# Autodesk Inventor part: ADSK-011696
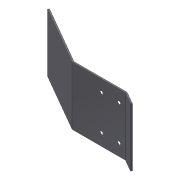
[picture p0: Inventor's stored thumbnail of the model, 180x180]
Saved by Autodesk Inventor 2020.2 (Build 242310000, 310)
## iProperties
Created: 2000-03
Part Number: ADSK-011696
Document SubType Name: Modeling
Designer: sspink
Material: Pearson Stainless Steel
Density: 1 g/cm^3
Sheet Metal Rule: Stahlblech 1.0312 - DC05 -   3.0 mm
Appearance: Pearson-Stainless
Mass: 126.696 g
Surface Area: 877.094 cm^2
Volume: 126.696 cm^3
Flat Pattern Width: 12.7 cm
Flat Pattern Length: 33.4701 cm
Flat Pattern Area: 425.07 cm^2
Sheet Metal Width: 127,000 mm
Sheet Metal Length: 334,701 mm
Sheet Metal Area: 42507,003 mm^2
Control State: 0
Master: False
Checked Out: False
Shininess: 57.0
Length Units: 11269
Angle Units: 11279
Time Units: 11290
Mass Units: 11283
Length Display Precision: 3
Angle Display Precision: 2
Compacted: True
Cutlength: 704 SI (20.25 X 34.75)
Material Desc: SHEET,HRS,11 GA
Material_Number: Axxxxxx
Dimensions: 127x90,7x312,9 mm
Mass: 0,127 kg
G_L: 127x334,7 mm
Thickness: 3,000 mm
Semi finished: Stahlblech 1.0312 - DC05 -   3.0 mm
VLT_Material: 1.0312 DC05
Density: 8.03
Volumn: 81.93532
Area: 537.0957000000001
PropertySet Name: Model Information
Author: sspink
Revision Number: -
Title: ADSK-011696
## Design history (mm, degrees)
node "Face1"
  sketch "Sketch1"
    geometry: L1 (-85, -63.5)-(85, -63.5); L2 (85, -63.5)-(85, 63.5); L3 (85, 63.5)-(-85, 63.5); L4 (-85, 63.5)-(-85, -63.5); 3 further points
    constraints: 8 end point, 2 midpoint, 2 parallel, 1 horizontal, 1 horizontal alignment, 1 perpendicular, 1 vertical alignment
    dimensions: "d0" = 127 distance between parallel lines of L1 L3; "d1" = 170 distance between parallel lines of L2 L4
node "Hole1" dims "d13" = 6.6, "d14" = 12.6, "d15" = 6.35, "d16" = 90 deg, "d17" = 19.05, "d18" = 118 deg, "d35" = 6
  sketch "Sketch4"
    geometry: L1 (0, 0)-(0, 127) reference; L2 (63, 101.5)-(25, 101.5); L3 (25, 101.5)-(25, 25.5); L4 (25, 25.5)-(63, 25.5); L5 (63, 25.5)-(63, 101.5); L6 (170, 127)-(170, 0) reference; 4 further points
    constraints: 8 end point, 3 horizontal alignment, 2 midpoint, 2 parallel, 2 vertical alignment, 1 horizontal, 1 perpendicular
    dimensions: "d19" = 25 distance from line of point (25, 101.5) L1; "d33" = 76 distance of L4.end L2.start; "d34" = 38 distance of L2.start L2.end
node "Flange1"
  node "Bend1" dims "d3" = 25, "d4" = 30 deg, "d5" = 3 (= BendRadius), "d24" = 3 (= BendReliefWidth), "d25" = 1.5 (= BendReliefDepth), "d26" = 6 (= MinimumRemnant), "d30" = 3 (= Thickness), "d31" = 3 (= TransitionRadius), "SeamGap" = 0.00508
node "Flange2"
  node "Bend2" dims "d6" = 140, "d7" = 30 deg, "d8" = 3 (= BendRadius), "d27" = 3 (= BendReliefWidth), "d28" = 1.5 (= BendReliefDepth), "d29" = 6 (= MinimumRemnant), "d30" = 3 (= Thickness), "d32" = 3 (= TransitionRadius), "SeamGap" = 0.00508
node "Solide1"
node "Corps solides"
node "Corps surfaciques"
node "Plate1" dims "d30" = 3 (= Thickness)
sketch "Sketch2"
  geometry: L1 (127, 0)-(127, 25); L2 (127, 25)-(0, 25); 1 other entity
  constraints: 4 end point, 4 other
node "Plate2" dims "d3" = 25, "d4" = 30 deg, "d5" = 3 (= BendRadius), "d24" = 3 (= BendReliefWidth), "d25" = 1.5 (= BendReliefDepth), "d26" = 6 (= MinimumRemnant), "d30" = 3 (= Thickness), "d31" = 3 (= TransitionRadius), "SeamGap" = 0.00508
sketch "Sketch3"
  geometry: L1 (-127, 0)-(-127, -140); L2 (-127, -140)-(0, -140); 1 other entity
  constraints: 4 end point, 4 other
node "Plate3" dims "d6" = 140, "d7" = 30 deg, "d8" = 3 (= BendRadius), "d27" = 3 (= BendReliefWidth), "d28" = 1.5 (= BendReliefDepth), "d29" = 6 (= MinimumRemnant), "d30" = 3 (= Thickness), "d32" = 3 (= TransitionRadius), "SeamGap" = 0.00508
feature "Definition1"
other parameters: "Thickness" = 3 (derived), "BendRadius" = 3 (= Thickness), "BendReliefWidth" = 3 (= Thickness), "BendReliefDepth" = 1.5 (= 0.5 x Thickness), "CornerReliefSize" = 12 (= 4 x Thickness), "MinimumRemnant" = 6 (= 2 x Thickness), "d2" = 3 (= BendRadius), "TransitionRadius" = 3 (= BendRadius), "TailleRayonJacobi" = 3 (= BendRadius), "TailleJeu" = 3 (= Thickness), "KFaktor" = 4.4, "BendRadius" = 3, "BendReliefDepth" = 1.5, "BendReliefWidth" = 3, "CornerReliefSize" = 12, "MinimumRemnant" = 6, "TailleJeu" = 3, "TailleRayonJacobi" = 3, "Thickness" = 3, "TransitionRadius" = 3
